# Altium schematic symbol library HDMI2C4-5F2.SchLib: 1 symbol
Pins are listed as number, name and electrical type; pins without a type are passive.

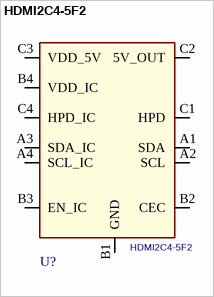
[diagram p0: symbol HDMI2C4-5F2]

## HDMI2C4-5F2
designator U?
footprint ST_CSP12N50P3x4_213x149x60
pins: A1 SDA, A2 SCL, A3 SDA_IC, A4 SCL_IC, B1 GND, B2 CEC, B3 EN_IC, B4 VDD_IC, C1 HPD, C2 5V_OUT, C3 VDD_5V, C4 HPD_IC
